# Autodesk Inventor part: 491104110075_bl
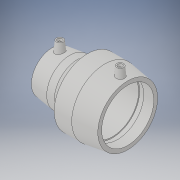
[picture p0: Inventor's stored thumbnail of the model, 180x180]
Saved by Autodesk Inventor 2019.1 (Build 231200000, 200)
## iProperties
Created: 2017-06
Part Number: 491104110075_bl
Material: Generic
Description: PLASSON REDUCING COUPLER 110-75
Document SubType Name: Modeling
Designer: KIM
Mass: 54.8237 g
Surface Area: 155.252 cm^2
Volume: 54.8237 cm^3
Density: 1 g/cm^3
Appearance: Default
Author: KIM
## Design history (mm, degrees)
derived "491104.ipt"
feature "Solid1::491104.ipt" dims "ScaleForDerivedMember" = 10
tag "TaggingFeature1"
body "Solid1"
other parameters: "d0" = 159 [user parameter], "d2" = 98 [user parameter], "d3" = 62 [user parameter], "d4" = 37.2 [user parameter], "d5" = 88.2 [user parameter], "d7" = 75 [user parameter], "d8" = 168 deg [user parameter], "d10" = 24.8 [user parameter], "d11" = 8.26667 [user parameter], "d13" = 159 [user parameter], "d14" = 17.6296 [user parameter], "d15" = 62 [user parameter], "d18" = 75 [user parameter], "d19" = 3.1 [user parameter], "d20" = 168 deg [user parameter], "d22" = 108.92847 [user parameter], "d25" = 135 deg [user parameter], "d29" = 66 [user parameter], "d30" = 15 [user parameter], "d31" = 63.6 [user parameter], "d34" = 6 deg [user parameter], "d35" = 15 [user parameter], "d38" = 24.75 [user parameter], "d39" = 5 deg [user parameter], "d41" = 4 [user parameter], "d42" = 14 [user parameter], "d43" = 0 [user parameter], "d45" = 4 [user parameter], "d46" = 14 [user parameter], "d47" = 0 [user parameter], "d48" = 98 [user parameter], "d52" = 67.5 [user parameter], "d53" = 32 [user parameter], "d54" = 10.66667 [user parameter], "d55" = 168 deg [user parameter], "d56" = 48 [user parameter], "d58" = 126 [user parameter], "d59" = 3.1 [user parameter], "d60" = 135 deg [user parameter], "d61" = 83 [user parameter], "d62" = 15 [user parameter], "d64" = 4 [user parameter], "d66" = 5 deg [user parameter], "d67" = 14 [user parameter], "d68" = 0 [user parameter], "d69" = 63.6 [user parameter], "d70" = 98 [user parameter], "d73" = 131.6 [user parameter], "d76" = 3.1 [user parameter], "d77" = 168 deg [user parameter], "d79" = 3.1 [user parameter], "d81" = 67.5 [user parameter], "d82" = 92.12 [user parameter], "d83" = 120 deg [user parameter], "d88" = 15 [user parameter], "d89" = 22.5 [user parameter], "d90" = 5 deg [user parameter], "d92" = 4 [user parameter], "d93" = 14 [user parameter], "d94" = 0 [user parameter], "d95" = 3 [user parameter], "d96" = 0 [user parameter], "d97" = 3 [user parameter], "d98" = 0 [user parameter], "d99" = 17.98 [user parameter], "d100" = 4.495 [user parameter], "d101" = 89.3564 [user parameter], "d102" = 20 deg [user parameter], "d103" = 23.2 [user parameter], "d104" = 5.8 [user parameter], "d105" = 127.652 [user parameter], "d106" = 3.60705 [user parameter], "d107" = 3 [user parameter], "d108" = 0 [user parameter], "d109" = 3 [user parameter], "d110" = 0 [user parameter], "d_1" = 75 [user parameter], "L_" = 159 [user parameter], "L_2" = 62 [user parameter], "D_1" = 98 [user parameter], "A_1" = 66 [user parameter], "d_2" = 12 [user parameter], "A_" = 83 [user parameter]
